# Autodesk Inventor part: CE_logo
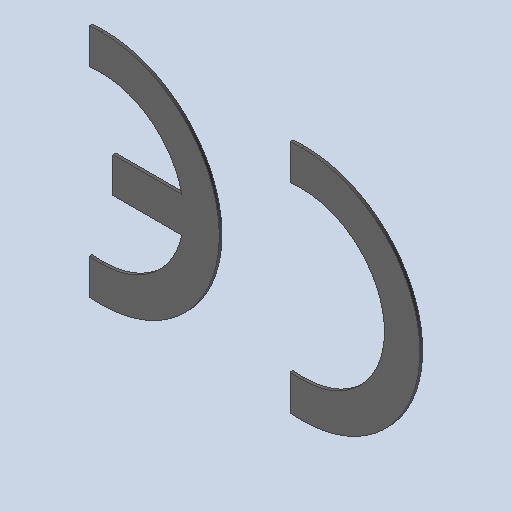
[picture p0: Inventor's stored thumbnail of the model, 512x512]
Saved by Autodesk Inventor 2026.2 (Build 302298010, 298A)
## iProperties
Created: 2026-10
Part Number: CE_logo
Material: Générique
Document SubType Name: Modeling
Designer: mel
Density: 1 g/cm^3
Appearance: Par défaut
Author: mel
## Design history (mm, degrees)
feature "Base1"
feature "Base2"
node "Solide1"
node "Solide2"
